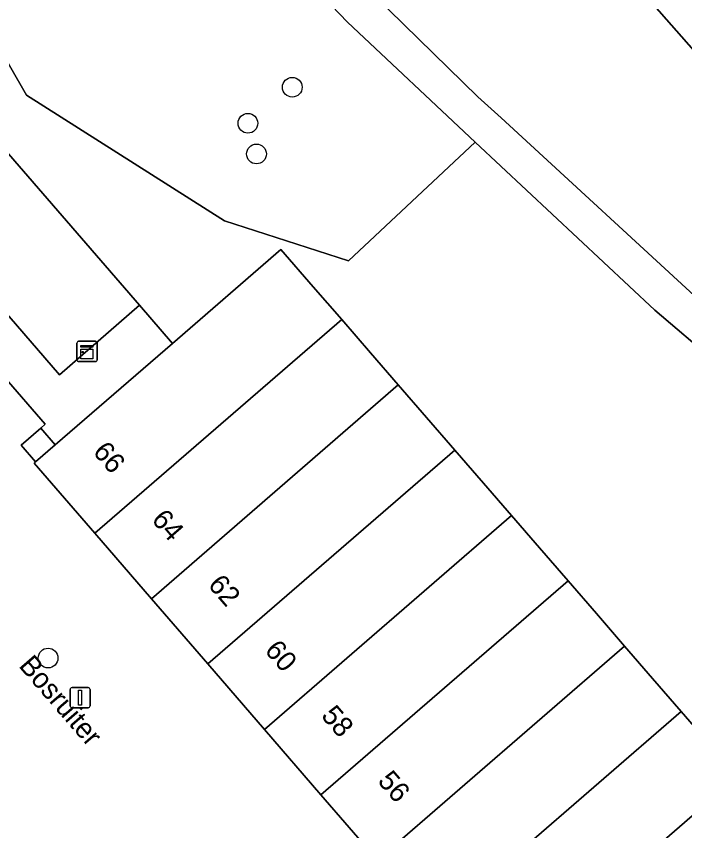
# Model space of a CAD drawing. Extents: x 156661 to 157576, y 383570 to 384425.
# Drawn here: x 156923.71 to 156956.84, y 384251.22 to 384291.58 of the extents above; entities that cross this region are included whole.
import ezdxf

# ---------------------------------------------------------------- set-up
doc = ezdxf.new("R2010")
doc.units = 0
for name, color, linetype in [('IMGEO_Boom', 7, 'Continuous'), ('IMGEO_Groenvoorziening', 7, 'Continuous'), ('IMGEO_Houtwal', 7, 'Continuous'), ('IMGEO_Kast', 7, 'Continuous'), ('IMGEO_Lichtmast', 7, 'Continuous'), ('IMGEO_Loofbos', 7, 'Continuous'), ('IMGEO_Muur', 7, 'Continuous'), ('IMGEO_Openbare_ruimte_label', 7, 'Continuous'), ('IMGEO_Pand', 7, 'Continuous'), ('IMGEO_Pand_nummerreeks', 7, 'Continuous'), ('IMGEO_Terreindeel_gesloten', 7, 'Continuous'), ('IMGEO_Voetpad_gesloten', 7, 'Continuous'), ('IMGEO_Voetpad_halfverhard', 7, 'Continuous'), ('IMGEO_Voetpad_open', 7, 'Continuous')]:
    doc.layers.add(name, color=color, linetype=linetype)

msp = doc.modelspace()

# ---------------------------------------------------------------- linework, layer by layer
at = {"layer": 'IMGEO_Boom'}
for centre in [(156937.391, 384288.061), (156935.191, 384286.274), (156935.618, 384284.752), (156925.29, 384259.773)]:
    msp.add_circle(centre, 0.489, dxfattribs=at)
at = {"layer": 'IMGEO_Groenvoorziening'}
for points in [[(156958.347, 384274.467), (156955.359, 384277.019), (156946.464, 384285.343), (156940.187, 384279.465), (156934.032, 384281.434), (156924.213, 384287.669), (156921.611, 384292.197)], [(156920.225, 384288.334), (156929.811, 384277.257), (156931.448, 384275.362), (156936.831, 384280.021), (156938.435, 384278.17), (156939.841, 384276.547), (156941.265, 384274.904), (156942.642, 384273.315), (156944.041, 384271.7), (156945.442, 384270.083), (156946.871, 384268.435), (156948.256, 384266.836), (156949.642, 384265.236), (156951.063, 384263.597), (156952.468, 384261.976), (156953.864, 384260.365), (156955.252, 384258.763), (156956.664, 384257.133), (156958.073, 384255.507)]]:
    msp.add_lwpolyline(points, dxfattribs=at)
at = {"layer": 'IMGEO_Houtwal'}
msp.add_lwpolyline([(156931.893, 384319.271), (156933.486, 384317.366), (156941.083, 384308.281), (156959.022, 384287.93), (156962.788, 384283.898), (156964.732, 384281.224), (156967.395, 384278.643), (156975.024, 384271.247), (156978.622, 384265.56)], dxfattribs=at)
at = {"layer": 'IMGEO_Kast'}
for p, q in [((156926.718, 384274.545), (156926.718, 384275.386)), ((156926.718, 384275.386), (156926.718, 384274.545)), ((156926.793, 384275.47), (156927.634, 384275.47)), ((156927.634, 384275.47), (156926.793, 384275.47)), ((156927.718, 384275.395), (156927.718, 384274.554)), ((156927.718, 384274.554), (156927.718, 384275.395)), ((156927.643, 384274.47), (156926.802, 384274.47)), ((156926.802, 384274.47), (156927.643, 384274.47))]:
    msp.add_line(p, q, dxfattribs=at)
for points in [[(156926.913, 384275.26), (156927.513, 384275.26), (156927.513, 384275.175), (156926.913, 384275.175), (156926.913, 384275.26)], [(156926.913, 384275.085), (156927.513, 384275.085), (156927.513, 384274.596), (156926.913, 384274.596), (156926.913, 384275.085)]]:
    msp.add_lwpolyline(points, dxfattribs=at)
msp.add_circle((156926.997, 384274.934), 0.0377, dxfattribs=at)
for centre, start, end in [((156926.796, 384275.392), 92.4484, 184.2845), ((156926.796, 384275.392), 92.4484, 184.2845), ((156927.64, 384275.392), 2.4484, 94.2845), ((156927.64, 384275.392), 2.4484, 94.2845), ((156926.796, 384274.548), 182.4484, 274.2845), ((156926.796, 384274.548), 182.4484, 274.2845), ((156927.64, 384274.548), 272.4484, 4.2845), ((156927.64, 384274.548), 272.4484, 4.2845)]:
    msp.add_arc(centre, 0.0779, start, end, dxfattribs=at)
at = {"layer": 'IMGEO_Lichtmast'}
for p, q in [((156926.378, 384257.415), (156926.378, 384258.215)), ((156926.378, 384258.215), (156926.378, 384257.415)), ((156926.478, 384258.315), (156927.268, 384258.315)), ((156927.268, 384258.315), (156926.478, 384258.315)), ((156927.368, 384258.215), (156927.368, 384257.415)), ((156927.368, 384257.415), (156927.368, 384258.215)), ((156927.268, 384257.315), (156926.478, 384257.315)), ((156926.478, 384257.315), (156927.268, 384257.315))]:
    msp.add_line(p, q, dxfattribs=at)
msp.add_lwpolyline([(156926.798, 384258.19), (156926.948, 384258.19), (156926.948, 384257.44), (156926.798, 384257.44), (156926.798, 384258.19)], dxfattribs=at)
for centre, start, end in [((156926.478, 384258.215), 90, 180), ((156926.478, 384258.215), 90, 180), ((156927.268, 384258.215), 0, 90), ((156927.268, 384258.215), 360, 90), ((156926.478, 384257.415), 180, 270), ((156926.478, 384257.415), 180, 270), ((156927.268, 384257.415), 270, 0), ((156927.268, 384257.415), 270, 0)]:
    msp.add_arc(centre, 0.1, start, end, dxfattribs=at)
at = {"layer": 'IMGEO_Loofbos'}
for points in [[(156978.622, 384265.56), (156975.024, 384271.247), (156967.395, 384278.643), (156964.732, 384281.224), (156962.788, 384283.898), (156959.022, 384287.93), (156941.083, 384308.281)], [(156931.33, 384305.695), (156934.402, 384301.517), (156936.828, 384297.951), (156940.712, 384293.341), (156946.593, 384287.588), (156947.738, 384286.536), (156957.949, 384277.16), (156960.969, 384274.816), (156969.206, 384269.258), (156974.485, 384265.285), (156978.508, 384262.205), (156978.718, 384262.506)], [(156925.888, 384305.399), (156923.23, 384303.234), (156924.705, 384301.55), (156920.266, 384297.637), (156922.327, 384295.29), (156923.556, 384293.891), (156921.611, 384292.197), (156924.213, 384287.669), (156934.032, 384281.434), (156940.187, 384279.465), (156946.464, 384285.343), (156940.124, 384291.277), (156935.757, 384295.859)]]:
    msp.add_lwpolyline(points, dxfattribs=at)
at = {"layer": 'IMGEO_Muur'}
for points in [[(156924.923, 384271.172), (156925.147, 384271.369), (156923.11, 384273.714)], [(156923.948, 384270.32), (156924.923, 384271.172)]]:
    msp.add_lwpolyline(points, dxfattribs=at)
at = {"layer": 'IMGEO_Pand'}
for points in [[(156939.841, 384276.547), (156938.435, 384278.17), (156936.831, 384280.021), (156931.448, 384275.362), (156925.642, 384270.338), (156924.671, 384269.498), (156924.595, 384269.432), (156927.603, 384265.957)], [(156939.841, 384276.547), (156927.603, 384265.957), (156930.409, 384262.715), (156942.642, 384273.315), (156941.265, 384274.904)], [(156930.409, 384262.715), (156933.209, 384259.481), (156945.442, 384270.083), (156944.041, 384271.7), (156942.642, 384273.315)], [(156948.256, 384266.836), (156946.871, 384268.435), (156945.442, 384270.083), (156933.209, 384259.481), (156936.014, 384256.239)], [(156938.813, 384253.005), (156951.063, 384263.597), (156949.642, 384265.236), (156948.256, 384266.836), (156936.014, 384256.239)], [(156951.063, 384263.597), (156938.813, 384253.005), (156941.619, 384249.764), (156953.864, 384260.365), (156952.468, 384261.976)], [(156953.864, 384260.365), (156941.619, 384249.764), (156944.424, 384246.522), (156956.664, 384257.133), (156955.252, 384258.763)], [(156959.465, 384253.901), (156958.073, 384255.507), (156956.664, 384257.133), (156944.424, 384246.522), (156947.224, 384243.288)], [(156950.03, 384240.046), (156962.265, 384250.669), (156960.852, 384252.3), (156959.465, 384253.901), (156947.224, 384243.288)]]:
    msp.add_lwpolyline(points, close=True, dxfattribs=at)
at = {"layer": 'IMGEO_Terreindeel_gesloten'}
msp.add_lwpolyline([(156924.923, 384271.172), (156923.948, 384270.32), (156924.671, 384269.498), (156925.642, 384270.338)], close=True, dxfattribs=at)
at = {"layer": 'IMGEO_Voetpad_gesloten'}
msp.add_lwpolyline([(156916.278, 384284.895), (156925.856, 384273.817), (156929.811, 384277.257), (156920.225, 384288.334), (156918.639, 384286.952)], close=True, dxfattribs=at)
at = {"layer": 'IMGEO_Voetpad_halfverhard'}
for points in [[(156947.738, 384286.536), (156946.593, 384287.588), (156940.712, 384293.341), (156936.828, 384297.951), (156934.402, 384301.517), (156931.33, 384305.695)], [(156929.29, 384304.956), (156930.652, 384303.568), (156935.757, 384295.859), (156940.124, 384291.277), (156946.464, 384285.343), (156955.359, 384277.019), (156958.347, 384274.467), (156960.609, 384272.783), (156967.174, 384268.505), (156973.154, 384264.094), (156977.53, 384260.641), (156978.186, 384260.123), (156983.634, 384255.146), (156989.755, 384249.711), (156995.848, 384243.123), (157001.139, 384237.036), (157008.158, 384228.713), (157012.721, 384223.099), (157017.805, 384217.82)], [(157023.321, 384214.775), (157013.259, 384225.25), (156997.37, 384244.407), (156984.682, 384256.939), (156980.47, 384260.703), (156978.508, 384262.205), (156974.485, 384265.285), (156969.206, 384269.258), (156960.969, 384274.816), (156957.949, 384277.16), (156947.738, 384286.536)], [(156941.619, 384249.764), (156938.813, 384253.005), (156936.014, 384256.239), (156933.209, 384259.481), (156930.409, 384262.715), (156927.603, 384265.957), (156924.595, 384269.432), (156924.671, 384269.498), (156923.948, 384270.32), (156924.923, 384271.172), (156925.147, 384271.369), (156923.11, 384273.714)]]:
    msp.add_lwpolyline(points, dxfattribs=at)
at = {"layer": 'IMGEO_Voetpad_open'}
msp.add_lwpolyline([(156914.55, 384283.577), (156914.83, 384283.252), (156923.04, 384273.795), (156923.11, 384273.714), (156925.147, 384271.369), (156924.923, 384271.172), (156925.642, 384270.338), (156931.448, 384275.362), (156929.811, 384277.257), (156925.856, 384273.817), (156916.278, 384284.895), (156916.18, 384284.984)], close=True, dxfattribs=at)

# ---------------------------------------------------------------- texts
at = {"layer": 'IMGEO_Openbare_ruimte_label'}
msp.add_text('Bosruiter', height=1, rotation=310.8624, dxfattribs=at).set_placement((156923.795, 384259.374))
at = {"layer": 'IMGEO_Pand_nummerreeks'}
for s, p in [('66', (156927.466, 384269.966)), ('64', (156930.373, 384266.607)), ('62', (156933.171, 384263.374)), ('60', (156935.98, 384260.129)), ('58', (156938.782, 384256.891)), ('56', (156941.582, 384253.656))]:
    msp.add_text(s, height=1, rotation=310.8765, dxfattribs=at).set_placement(p)

doc.saveas('drawing.dxf')
